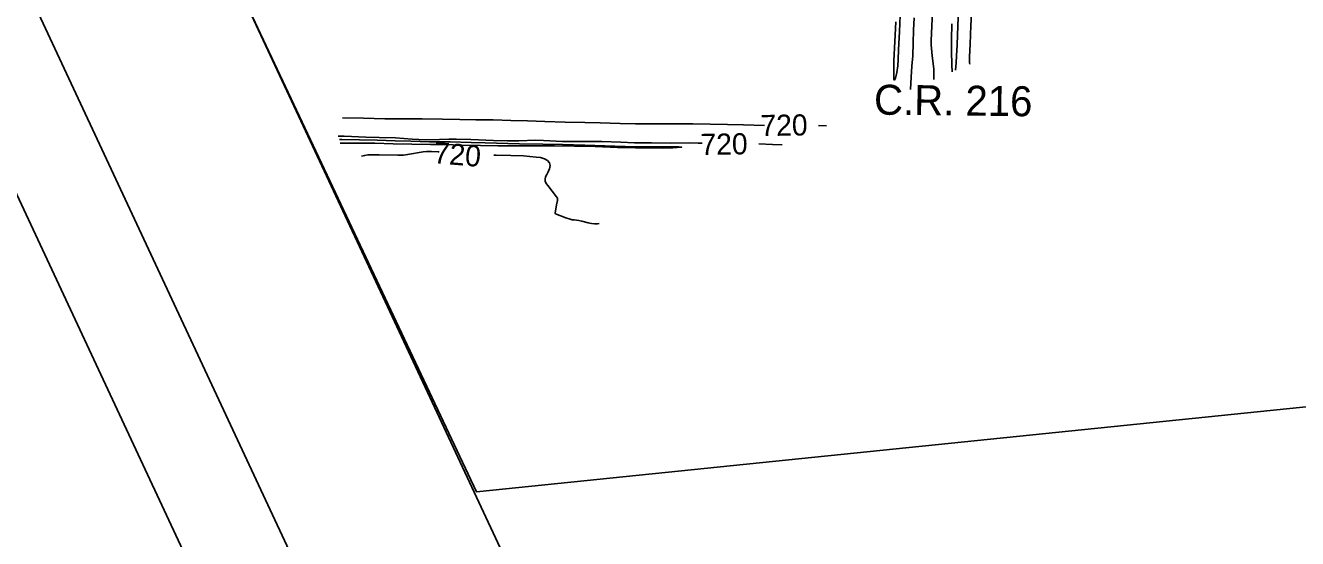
# Model space of a CAD drawing. Extents: x -310467766 to 17062430, y -322263100 to 8322522.
# Drawn here: x 1392973 to 1394957, y 570642 to 571443 of the extents above; entities that cross this region are included whole.
import ezdxf

# ---------------------------------------------------------------- set-up
doc = ezdxf.new("R2010")
doc.units = 0
for name, color, linetype in [('DT_X_Contour_Minor', 7, 'Continuous'), ('Level 19', 7, 'Continuous'), ('Level 40', 7, 'Continuous'), ('SC_Scratch1', 7, 'Continuous'), ('SH_Border', 7, 'Continuous'), ('SH_Cut_Line', 7, 'Continuous')]:
    doc.layers.add(name, color=color, linetype=linetype)

msp = doc.modelspace()

# ---------------------------------------------------------------- linework, layer by layer
at = {"layer": 'DT_X_Contour_Minor'}
for points in [[(1394441.3, 571780.2), (1394440.6, 571768.8), (1394438.8, 571736.5), (1394437.6, 571711.2), (1394436.6, 571686.1), (1394435.6, 571660.3), (1394434.5, 571628.4), (1394433.3, 571595.9), (1394432.3, 571571.2), (1394431.1, 571544.6), (1394429.9, 571519.3), (1394429, 571493.4), (1394428, 571469.1), (1394427, 571442.7), (1394426, 571413), (1394425.1, 571395.6), (1394424.6, 571384.9), (1394423.7, 571373.5)], [(1394394, 571640.3), (1394394.1, 571635.8), (1394393.1, 571603.8), (1394392, 571584.5), (1394391.5, 571578.5), (1394391.5, 571571.8), (1394392.7, 571551.9), (1394394.1, 571531.2), (1394394, 571524), (1394393.2, 571516.9), (1394390.8, 571501.7), (1394388, 571483.3), (1394387.5, 571476.5), (1394387.1, 571453.7), (1394385.4, 571419.7), (1394385.6, 571413), (1394387.2, 571395.8), (1394389.4, 571375.4), (1394389.7, 571369.3), (1394389.9, 571363.3), (1394389.8, 571358.9)], [(1394336.9, 571458.9), (1394336.1, 571433.8), (1394334.8, 571405.3), (1394334.2, 571390.2), (1394333.3, 571380.2), (1394331.8, 571369.7), (1394329.8, 571360.9), (1394329, 571358.8), (1394328.5, 571358.1), (1394327.6, 571358.2), (1394327.3, 571359.2), (1394327.1, 571361.9), (1394327.1, 571378.5), (1394327.3, 571388.1), (1394328.7, 571418.1), (1394330.2, 571448.8)], [(1394353.4, 571343.2), (1394354.3, 571362.7), (1394355.6, 571379.7), (1394356.9, 571396.1), (1394357.4, 571416.1), (1394357.9, 571435.9), (1394359.1, 571455.3)], [(1394448.7, 571469.9), (1394447.3, 571443.1), (1394446.1, 571414.1), (1394445.1, 571394.1), (1394445.5, 571384.8), (1394445.8, 571383)], [(1394418, 571371.1), (1394417.6, 571381.7), (1394417.1, 571403.1), (1394417.2, 571421.6), (1394417.9, 571446)], [(1394125.8, 571287.3), (1394092.7, 571287.9), (1394067.6, 571288.4), (1394040.8, 571289), (1394013.8, 571289.5), (1393987.5, 571289.5), (1393956.1, 571289.7), (1393924.5, 571289.9), (1393900.5, 571290.3), (1393869.2, 571291.2), (1393845.6, 571291.6), (1393814.8, 571292.3), (1393782.8, 571293.4), (1393755.8, 571294.3), (1393730.1, 571294.9), (1393702.3, 571295.7), (1393675.4, 571296.2), (1393650.5, 571296.7), (1393623.4, 571297.2), (1393591.4, 571297.5), (1393563.7, 571297.6), (1393533.5, 571297.7), (1393500, 571298.4), (1393467.3, 571299.2)], [(1394222.4, 571286.8), (1394209.9, 571287)], [(1393460.7, 571270.7), (1393469.8, 571270.4), (1393503.7, 571268.8), (1393524.8, 571268.5), (1393550, 571267.7), (1393576.2, 571266), (1393596.7, 571264.6), (1393618.5, 571265.4), (1393633, 571265.8), (1393644.7, 571265.6), (1393667.4, 571265), (1393703.1, 571263.7), (1393724.8, 571263), (1393742.3, 571263.4), (1393768.8, 571264.1), (1393780.8, 571263.7), (1393810.6, 571262.3), (1393824.7, 571261.9), (1393848.6, 571262), (1393871.8, 571262.3), (1393901.5, 571260.9), (1393922.6, 571260), (1393949.5, 571259.8), (1393979, 571259.6), (1394008.1, 571259.8), (1394021.9, 571259.7), (1394028.1, 571259.5)], [(1393464, 571259.7), (1393470.3, 571259.6), (1393497.6, 571259.6), (1393517.8, 571259.4), (1393546.5, 571258.5), (1393575.3, 571257.8), (1393604.9, 571257.6), (1393627.2, 571257.3), (1393653.7, 571256.6), (1393682.6, 571256), (1393709.5, 571255.6), (1393744.3, 571255.5), (1393774.3, 571255.5), (1393798.3, 571255.4), (1393829.3, 571254.8), (1393861.5, 571254.1), (1393896.3, 571252.9), (1393924.4, 571252.3), (1393953.4, 571252), (1393966.6, 571251.6), (1393982.4, 571252.3), (1393996.4, 571253.4), (1393991.7, 571253.6), (1393958.1, 571253.7), (1393930.4, 571254), (1393908.5, 571254.4), (1393876.7, 571255.4), (1393845.1, 571256.3), (1393810.7, 571257.3), (1393780, 571258.2), (1393743.3, 571258.6), (1393725.1, 571258.9), (1393689.9, 571259.9), (1393668.2, 571260.6), (1393635.2, 571261.4), (1393603.3, 571261.5), (1393574, 571262.4), (1393549.7, 571263.3), (1393521.3, 571264), (1393493.7, 571264.8), (1393466.5, 571265.4), (1393462.6, 571265.4)], [(1394116.7, 571258.5), (1394137.8, 571257.6), (1394153.1, 571256.9)], [(1393618.1, 571245.7), (1393616.9, 571245.8), (1393606.2, 571246.4), (1393601.7, 571246.6), (1393598.5, 571246.4), (1393593.4, 571245.8), (1393569, 571241.7), (1393562.7, 571241), (1393553.8, 571240.8), (1393524.8, 571241.2), (1393511.9, 571241.4), (1393507, 571241.2), (1393502.2, 571240.5), (1393496.9, 571239.3)], [(1393867.6, 571133.9), (1393865.2, 571133.7), (1393860.6, 571133.8), (1393855.6, 571134.2), (1393850.3, 571135), (1393840.5, 571137.5), (1393836.1, 571138.7), (1393828.7, 571139.7), (1393825.5, 571140), (1393822.6, 571140.7), (1393815.8, 571143), (1393799.8, 571149.3), (1393799.2, 571150.1), (1393799.2, 571150.9), (1393799.9, 571156.5), (1393801.3, 571163.2), (1393802.8, 571169.9), (1393802.8, 571172.1), (1393802.5, 571173.7), (1393801.3, 571175.7), (1393787.6, 571193.3), (1393785.2, 571196.7), (1393783.7, 571200), (1393783.4, 571203.2), (1393784.2, 571206.7), (1393785.9, 571210.6), (1393788.3, 571215), (1393790.4, 571219.7), (1393791.4, 571224.4), (1393790.3, 571228.7), (1393787.2, 571232.3), (1393782.4, 571235.1), (1393776.3, 571236.9), (1393769.6, 571237.9), (1393749.6, 571239.7), (1393730, 571240.2), (1393707.1, 571240.7), (1393703.2, 571240.8)]]:
    msp.add_lwpolyline(points, dxfattribs=at)
at = {"layer": 'SC_Scratch1'}
msp.add_lwpolyline([(1392212.4, 573822.1), (1393676.3, 570715.4), (1396857.5, 571041.4), (1399761.2, 572912.7), (1399601.4, 573251.9), (1400998.4, 575913.7), (1400551.7, 577289.3)], close=True, dxfattribs=at)
at = {"layer": 'SH_Border'}
for points in [[(1391939.2, 574432), (1400639.7, 578489.1), (1403302.2, 572779.4), (1394601.7, 568722.3)], [(1391667.3, 574305.2), (1391939.2, 574432), (1394601.7, 568722.3), (1394329.8, 568595.5)]]:
    msp.add_lwpolyline(points, close=True, dxfattribs=at)
at = {"layer": 'SH_Cut_Line'}
msp.add_lwpolyline([(1394257.2, 568396.1), (1403501.6, 572706.8), (1400712.3, 578688.5), (1391467.9, 574377.8)], close=True, dxfattribs=at)

# ---------------------------------------------------------------- texts
at = {"layer": 'Level 19'}
for rotation, p in [(0.8995, (1394119.4, 571270.5)), (355.1651, (1393608.5, 571228.5)), (0.9454, (1394025.9, 571241))]:
    msp.add_text('720', height=33, rotation=rotation, dxfattribs=at).set_placement(p)
at = {"layer": 'Level 40'}
msp.add_text('C.R. 216', height=46.8, rotation=359.3701, dxfattribs=at).set_placement((1394296.2, 571304.1))

doc.saveas('drawing.dxf')
